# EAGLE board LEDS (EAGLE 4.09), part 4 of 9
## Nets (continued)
N$Y.22: LED11.64.P$K LED11.65.P$K LED11.66.P$K LED11.67.P$K LED11.68.P$K LED11.69.P$K LED11.70.P$K LED11.71.P$K LED11.72.P$K LED11.73.P$K LED11.74.P$K LED11.75.P$K LED11.76.P$K LED11.77.P$K LED11.78.P$K LED11.79.P$K LED11.80.P$K LED11.81.P$K LED11.82.P$K LED11.83.P$K LED11.84.P$K LED11.85.P$K LED11.86.P$K LED11.87.P$K LED11.88.P$K LED11.89.P$K LED11.90.P$K LED11.91.P$K LED11.92.P$K LED11.93.P$K LED11.94.P$K LED11.95.P$K LED11.96.P$K LED11.97.P$K LED11.98.P$K LED11.99.P$K LED11.100.P$K LED11.101.P$K LED11.102.P$K LED11.103.P$K LED11.104.P$K LED11.105.P$K LED11.106.P$K LED11.107.P$K LED11.108.P$K LED11.109.P$K LED11.110.P$K LED11.111.P$K LED11.112.P$K LED11.113.P$K LED11.114.P$K LED11.115.P$K LED11.116.P$K LED11.117.P$K LED11.118.P$K LED11.119.P$K LED11.120.P$K LED11.121.P$K LED11.122.P$K LED11.123.P$K LED11.124.P$K LED11.125.P$K LED11.126.P$K LED11.127.P$K Y.22.P$
N$Y.23: LED12.64.P$K LED12.65.P$K LED12.66.P$K LED12.67.P$K LED12.68.P$K LED12.69.P$K LED12.70.P$K LED12.71.P$K LED12.72.P$K LED12.73.P$K LED12.74.P$K LED12.75.P$K LED12.76.P$K LED12.77.P$K LED12.78.P$K LED12.79.P$K LED12.80.P$K LED12.81.P$K LED12.82.P$K LED12.83.P$K LED12.84.P$K LED12.85.P$K LED12.86.P$K LED12.87.P$K LED12.88.P$K LED12.89.P$K LED12.90.P$K LED12.91.P$K LED12.92.P$K LED12.93.P$K LED12.94.P$K LED12.95.P$K LED12.98.P$K LED12.99.P$K LED12.100.P$K LED12.101.P$K LED12.102.P$K LED12.103.P$K LED12.104.P$K LED12.105.P$K LED12.106.P$K LED12.107.P$K LED12.108.P$K LED12.109.P$K LED12.110.P$K LED12.111.P$K LED12.112.P$K LED12.113.P$K LED12.114.P$K LED12.115.P$K LED12.116.P$K LED12.117.P$K LED12.118.P$K LED12.119.P$K LED12.120.P$K LED12.121.P$K LED12.122.P$K LED12.123.P$K LED12.124.P$K LED12.125.P$K LED12.126.P$K LED12.127.P$K Y.23.P$
N$Y.24: LED13.64.P$K LED13.65.P$K LED13.66.P$K LED13.67.P$K LED13.68.P$K LED13.69.P$K LED13.70.P$K LED13.71.P$K LED13.72.P$K LED13.73.P$K LED13.74.P$K LED13.75.P$K LED13.76.P$K LED13.77.P$K LED13.78.P$K LED13.79.P$K LED13.80.P$K LED13.81.P$K LED13.82.P$K LED13.83.P$K LED13.84.P$K LED13.85.P$K LED13.86.P$K LED13.87.P$K LED13.88.P$K LED13.89.P$K LED13.90.P$K LED13.91.P$K LED13.92.P$K LED13.93.P$K LED13.94.P$K LED13.95.P$K LED13.96.P$K LED13.97.P$K LED13.98.P$K LED13.99.P$K LED13.100.P$K LED13.101.P$K LED13.102.P$K LED13.103.P$K LED13.104.P$K LED13.105.P$K LED13.106.P$K LED13.107.P$K LED13.108.P$K LED13.109.P$K LED13.110.P$K LED13.111.P$K LED13.112.P$K LED13.113.P$K LED13.114.P$K LED13.115.P$K LED13.116.P$K LED13.117.P$K LED13.118.P$K LED13.119.P$K LED13.120.P$K LED13.121.P$K LED13.122.P$K LED13.123.P$K LED13.124.P$K LED13.125.P$K LED13.126.P$K LED13.127.P$K Y.24.P$
N$Y.25: LED14.64.P$K LED14.65.P$K LED14.66.P$K LED14.67.P$K LED14.68.P$K LED14.69.P$K LED14.70.P$K LED14.71.P$K LED14.72.P$K LED14.73.P$K LED14.74.P$K LED14.75.P$K LED14.76.P$K LED14.77.P$K LED14.78.P$K LED14.79.P$K LED14.80.P$K LED14.81.P$K LED14.82.P$K LED14.83.P$K LED14.84.P$K LED14.85.P$K LED14.86.P$K LED14.87.P$K LED14.88.P$K LED14.89.P$K LED14.90.P$K LED14.91.P$K LED14.92.P$K LED14.93.P$K LED14.94.P$K LED14.95.P$K LED14.97.P$K LED14.99.P$K LED14.100.P$K LED14.101.P$K LED14.102.P$K LED14.103.P$K LED14.104.P$K LED14.105.P$K LED14.106.P$K LED14.107.P$K LED14.108.P$K LED14.109.P$K LED14.110.P$K LED14.111.P$K LED14.112.P$K LED14.113.P$K LED14.114.P$K LED14.115.P$K LED14.116.P$K LED14.117.P$K LED14.118.P$K LED14.119.P$K LED14.120.P$K LED14.121.P$K LED14.122.P$K LED14.123.P$K LED14.124.P$K LED14.125.P$K LED14.126.P$K LED14.127.P$K Y.25.P$
N$Y.26: LED15.64.P$K LED15.65.P$K LED15.66.P$K LED15.67.P$K LED15.68.P$K LED15.69.P$K LED15.70.P$K LED15.71.P$K LED15.72.P$K LED15.73.P$K LED15.74.P$K LED15.75.P$K LED15.76.P$K LED15.77.P$K LED15.78.P$K LED15.79.P$K LED15.80.P$K LED15.81.P$K LED15.82.P$K LED15.83.P$K LED15.84.P$K LED15.85.P$K LED15.86.P$K LED15.87.P$K LED15.88.P$K LED15.89.P$K LED15.90.P$K LED15.91.P$K LED15.92.P$K LED15.93.P$K LED15.94.P$K LED15.95.P$K LED15.97.P$K LED15.98.P$K LED15.99.P$K LED15.100.P$K LED15.101.P$K LED15.102.P$K LED15.103.P$K LED15.104.P$K LED15.105.P$K LED15.106.P$K LED15.107.P$K LED15.108.P$K LED15.109.P$K LED15.110.P$K LED15.111.P$K LED15.112.P$K LED15.113.P$K LED15.114.P$K LED15.115.P$K LED15.116.P$K LED15.117.P$K LED15.118.P$K LED15.119.P$K LED15.120.P$K LED15.121.P$K LED15.122.P$K LED15.123.P$K LED15.124.P$K LED15.125.P$K LED15.126.P$K LED15.127.P$K Y.26.P$
N$Y.27: LED16.64.P$K LED16.65.P$K LED16.66.P$K LED16.67.P$K LED16.68.P$K LED16.69.P$K LED16.70.P$K LED16.71.P$K LED16.72.P$K LED16.73.P$K LED16.74.P$K LED16.75.P$K LED16.76.P$K LED16.77.P$K LED16.78.P$K LED16.79.P$K LED16.80.P$K LED16.81.P$K LED16.82.P$K LED16.83.P$K LED16.84.P$K LED16.85.P$K LED16.86.P$K LED16.87.P$K LED16.88.P$K LED16.89.P$K LED16.90.P$K LED16.91.P$K LED16.92.P$K LED16.93.P$K LED16.94.P$K LED16.95.P$K LED16.97.P$K LED16.98.P$K LED16.99.P$K LED16.100.P$K LED16.101.P$K LED16.102.P$K LED16.103.P$K LED16.104.P$K LED16.105.P$K LED16.106.P$K LED16.107.P$K LED16.108.P$K LED16.109.P$K LED16.110.P$K LED16.111.P$K LED16.112.P$K LED16.113.P$K LED16.114.P$K LED16.115.P$K LED16.116.P$K LED16.117.P$K LED16.118.P$K LED16.119.P$K LED16.120.P$K LED16.121.P$K LED16.122.P$K LED16.123.P$K LED16.124.P$K LED16.125.P$K LED16.126.P$K LED16.127.P$K Y.27.P$
N$Y.28: LED17.64.P$K LED17.65.P$K LED17.66.P$K LED17.67.P$K LED17.68.P$K LED17.69.P$K LED17.70.P$K LED17.71.P$K LED17.72.P$K LED17.73.P$K LED17.74.P$K LED17.75.P$K LED17.76.P$K LED17.77.P$K LED17.78.P$K LED17.79.P$K LED17.80.P$K LED17.81.P$K LED17.82.P$K LED17.83.P$K LED17.84.P$K LED17.85.P$K LED17.86.P$K LED17.87.P$K LED17.88.P$K LED17.89.P$K LED17.90.P$K LED17.91.P$K LED17.92.P$K LED17.93.P$K LED17.94.P$K LED17.95.P$K LED17.97.P$K LED17.98.P$K LED17.99.P$K LED17.100.P$K LED17.101.P$K LED17.102.P$K LED17.103.P$K LED17.104.P$K LED17.105.P$K LED17.106.P$K LED17.107.P$K LED17.108.P$K LED17.109.P$K LED17.110.P$K LED17.111.P$K LED17.112.P$K LED17.113.P$K LED17.114.P$K LED17.115.P$K LED17.116.P$K LED17.117.P$K LED17.118.P$K LED17.119.P$K LED17.120.P$K LED17.121.P$K LED17.122.P$K LED17.123.P$K LED17.124.P$K LED17.125.P$K LED17.126.P$K LED17.127.P$K Y.28.P$
N$Y.29: LED18.64.P$K LED18.65.P$K LED18.66.P$K LED18.67.P$K LED18.68.P$K LED18.69.P$K LED18.70.P$K LED18.71.P$K LED18.72.P$K LED18.73.P$K LED18.74.P$K LED18.75.P$K LED18.76.P$K LED18.77.P$K LED18.78.P$K LED18.79.P$K LED18.80.P$K LED18.81.P$K LED18.82.P$K LED18.83.P$K LED18.84.P$K LED18.85.P$K LED18.86.P$K LED18.87.P$K LED18.88.P$K LED18.89.P$K LED18.90.P$K LED18.91.P$K LED18.92.P$K LED18.93.P$K LED18.94.P$K LED18.95.P$K LED18.96.P$K LED18.98.P$K LED18.99.P$K LED18.100.P$K LED18.101.P$K LED18.102.P$K LED18.103.P$K LED18.104.P$K LED18.105.P$K LED18.106.P$K LED18.107.P$K LED18.108.P$K LED18.109.P$K LED18.110.P$K LED18.111.P$K LED18.112.P$K LED18.113.P$K LED18.114.P$K LED18.115.P$K LED18.116.P$K LED18.117.P$K LED18.118.P$K LED18.119.P$K LED18.120.P$K LED18.121.P$K LED18.122.P$K LED18.123.P$K LED18.124.P$K LED18.125.P$K LED18.126.P$K LED18.127.P$K Y.29.P$
N$Y.30: LED19.64.P$K LED19.65.P$K LED19.66.P$K LED19.67.P$K LED19.68.P$K LED19.69.P$K LED19.70.P$K LED19.71.P$K LED19.72.P$K LED19.73.P$K LED19.74.P$K LED19.75.P$K LED19.76.P$K LED19.77.P$K LED19.78.P$K LED19.79.P$K LED19.80.P$K LED19.81.P$K LED19.82.P$K LED19.83.P$K LED19.84.P$K LED19.85.P$K LED19.86.P$K LED19.87.P$K LED19.88.P$K LED19.89.P$K LED19.90.P$K LED19.91.P$K LED19.92.P$K LED19.93.P$K LED19.94.P$K LED19.96.P$K LED19.97.P$K LED19.98.P$K LED19.99.P$K LED19.100.P$K LED19.101.P$K LED19.102.P$K LED19.103.P$K LED19.104.P$K LED19.105.P$K LED19.106.P$K LED19.107.P$K LED19.108.P$K LED19.109.P$K LED19.110.P$K LED19.111.P$K LED19.112.P$K LED19.113.P$K LED19.114.P$K LED19.115.P$K LED19.116.P$K LED19.117.P$K LED19.118.P$K LED19.119.P$K LED19.120.P$K LED19.121.P$K LED19.122.P$K LED19.123.P$K LED19.124.P$K LED19.125.P$K LED19.126.P$K LED19.127.P$K Y.30.P$
N$Y.31: LED20.64.P$K LED20.65.P$K LED20.66.P$K LED20.67.P$K LED20.68.P$K LED20.69.P$K LED20.70.P$K LED20.71.P$K LED20.72.P$K LED20.73.P$K LED20.74.P$K LED20.75.P$K LED20.76.P$K LED20.77.P$K LED20.78.P$K LED20.79.P$K LED20.80.P$K LED20.81.P$K LED20.82.P$K LED20.83.P$K LED20.84.P$K LED20.85.P$K LED20.86.P$K LED20.87.P$K LED20.88.P$K LED20.89.P$K LED20.90.P$K LED20.91.P$K LED20.92.P$K LED20.93.P$K LED20.94.P$K LED20.96.P$K LED20.97.P$K LED20.98.P$K LED20.99.P$K LED20.100.P$K LED20.101.P$K LED20.102.P$K LED20.103.P$K LED20.104.P$K LED20.105.P$K LED20.106.P$K LED20.107.P$K LED20.108.P$K LED20.109.P$K LED20.110.P$K LED20.111.P$K LED20.112.P$K LED20.113.P$K LED20.114.P$K LED20.115.P$K LED20.116.P$K LED20.117.P$K LED20.118.P$K LED20.119.P$K LED20.120.P$K LED20.121.P$K LED20.122.P$K LED20.123.P$K LED20.124.P$K LED20.125.P$K LED20.126.P$K LED20.127.P$K Y.31.P$
N$Y.32: LED14.96.P$K
N$Y.33: LED14.98.P$K
N$Y.34: LED14.128.P$K
N$Y.35: LED14.129.P$K
N$Y.36: LED14.130.P$K
N$Y.37: LED14.131.P$K
N$Y.38: LED14.132.P$K
N$Y.39: LED14.133.P$K
S$2: LED0.12.P$K LED0.13.P$K LED0.14.P$K
S$3: LED0.62.P$A LED1.62.P$A
S$4: LED0.60.P$A LED1.60.P$A LED2.60.P$A
S$5: LED0.59.P$A LED1.59.P$A
S$6: LED3.57.P$A LED4.57.P$A
S$7: LED5.61.P$K LED5.62.P$K
S$8: LED2.62.P$A LED3.62.P$A
S$9: LED2.58.P$K LED2.59.P$K LED2.60.P$K LED2.61.P$K LED2.62.P$K
S$10: LED3.58.P$K LED3.59.P$K LED3.60.P$K LED3.61.P$K LED3.62.P$K
S$11: LED0.61.P$A LED1.61.P$A LED2.61.P$A LED3.61.P$A
S$12: LED0.57.P$A LED1.57.P$A LED2.57.P$A
S$13: LED0.56.P$A LED1.56.P$A LED2.56.P$A LED3.56.P$A X56.P$
S$14: LED7.61.P$K LED7.62.P$K LED7.63.P$K
S$15: LED6.61.P$K LED6.62.P$K LED6.63.P$K
S$16: LED1.61.P$K LED1.62.P$K
S$17: LED2.59.P$A LED3.59.P$A LED4.59.P$A
S$18: LED1.59.P$K LED1.60.P$K
S$19: LED0.55.P$A LED1.55.P$A LED2.55.P$A X55.P$
S$20: LED3.23.P$A LED4.23.P$A LED5.23.P$A
S$21: LED3.55.P$A LED4.55.P$A
S$22: LED1.54.P$A LED2.54.P$A LED3.54.P$A LED4.54.P$A
S$25: LED6.61.P$A LED7.61.P$A
S$26: LED8.62.P$K LED8.63.P$K
S$27: LED8.59.P$K LED8.60.P$K
S$28: LED4.56.P$A LED5.56.P$A
S$29: LED8.0.P$K LED8.1.P$K LED8.2.P$K LED8.3.P$K LED8.4.P$K LED8.5.P$K LED8.6.P$K LED8.7.P$K LED8.8.P$K LED8.9.P$K LED8.10.P$K LED8.11.P$K LED8.12.P$K LED8.13.P$K LED8.14.P$K LED8.15.P$K LED8.16.P$K LED8.17.P$K LED8.18.P$K LED8.19.P$K LED8.20.P$K LED8.21.P$K LED8.22.P$K LED8.23.P$K LED8.24.P$K LED8.25.P$K LED8.26.P$K LED8.27.P$K Y.8.P$
S$30: LED2.33.P$K LED2.34.P$K
S$31: LED6.23.P$A LED7.23.P$A LED8.23.P$A LED9.23.P$A
S$32: LED4.25.P$A LED5.25.P$A LED6.25.P$A
S$33: LED3.25.P$K LED3.26.P$K LED3.27.P$K LED3.28.P$K LED3.29.P$K LED3.30.P$K LED3.31.P$K
S$34: LED4.25.P$K LED4.26.P$K LED4.27.P$K LED4.28.P$K LED4.29.P$K LED4.30.P$K
S$35: LED4.26.P$A LED5.26.P$A
S$36: LED4.30.P$A
S$37: LED4.46.P$K LED4.47.P$K LED4.48.P$K LED4.49.P$K LED4.50.P$K LED4.51.P$K LED4.52.P$K LED4.53.P$K LED4.54.P$K LED4.55.P$K
S$38: LED5.26.P$K LED5.27.P$K LED5.28.P$K
S$39: LED6.41.P$K LED6.42.P$K LED6.43.P$K LED6.44.P$K LED6.45.P$K LED6.46.P$K LED6.47.P$K LED6.48.P$K
S$40: LED3.28.P$A LED4.28.P$A LED5.28.P$A
S$41: LED5.48.P$K LED5.49.P$K LED5.50.P$K LED5.51.P$K LED5.52.P$K LED5.53.P$K LED5.54.P$K LED5.55.P$K
S$42: LED5.36.P$A LED6.36.P$A
S$43: LED7.31.P$K LED7.33.P$K LED7.34.P$K LED7.35.P$K LED7.36.P$K LED7.37.P$K LED7.38.P$K LED7.39.P$K LED7.40.P$K LED7.41.P$K LED7.42.P$K LED7.43.P$K LED7.44.P$K LED7.45.P$K LED7.46.P$K LED7.47.P$K
S$44: LED4.31.P$A LED5.31.P$A LED6.31.P$A
S$45: LED4.34.P$K LED4.35.P$K
S$46: LED6.31.P$K
S$47: LED0.54.P$A X54.P$
S$48: LED5.33.P$K LED5.34.P$K LED5.35.P$K LED5.36.P$K
S$49: LED3.48.P$K LED3.49.P$K LED3.50.P$K LED3.51.P$K LED3.52.P$K LED3.53.P$K LED3.54.P$K LED3.55.P$K
S$50: LED4.24.P$A LED5.24.P$A LED6.24.P$A LED7.24.P$A LED8.24.P$A LED9.24.P$A LED10.24.P$A
S$51: LED1.54.P$K LED1.55.P$K LED1.56.P$K LED1.57.P$K
S$52: LED3.32.P$K LED3.33.P$K LED3.34.P$K
S$53: LED5.29.P$K LED5.31.P$K LED5.32.P$K
S$54: LED5.33.P$A LED6.33.P$A
S$55: LED2.42.P$K LED2.43.P$K LED2.44.P$K LED2.45.P$K LED2.46.P$K LED2.47.P$K LED2.48.P$K LED2.49.P$K LED2.50.P$K LED2.51.P$K LED2.52.P$K LED2.53.P$K LED2.54.P$K LED2.55.P$K LED2.56.P$K LED2.57.P$K
S$56: LED4.34.P$A LED5.34.P$A
S$57: LED4.31.P$K LED4.32.P$K LED4.33.P$K
S$58: LED5.32.P$A
S$59: LED1.19.P$A LED2.19.P$A LED3.19.P$A LED4.19.P$A LED5.19.P$A LED6.19.P$A LED7.19.P$A LED8.19.P$A LED9.19.P$A
S$60: LED6.33.P$K LED6.34.P$K LED6.35.P$K
S$61: LED10.0.P$K LED10.1.P$K LED10.2.P$K LED10.3.P$K LED10.4.P$K LED10.5.P$K LED10.6.P$K LED10.7.P$K LED10.8.P$K LED10.9.P$K LED10.10.P$K LED10.11.P$K LED10.12.P$K LED10.13.P$K LED10.14.P$K LED10.15.P$K LED10.16.P$K LED10.17.P$K LED10.18.P$K LED10.19.P$K LED10.20.P$K LED10.21.P$K LED10.22.P$K LED10.23.P$K LED10.24.P$K LED10.25.P$K LED10.26.P$K LED10.27.P$K LED10.28.P$K Y.10.P$
S$62: LED4.38.P$K LED4.39.P$K LED4.40.P$K
S$63: LED9.0.P$K LED9.1.P$K LED9.2.P$K LED9.3.P$K LED9.4.P$K LED9.5.P$K LED9.6.P$K LED9.7.P$K LED9.8.P$K LED9.9.P$K LED9.10.P$K LED9.11.P$K LED9.12.P$K LED9.13.P$K LED9.14.P$K LED9.15.P$K LED9.16.P$K LED9.17.P$K LED9.18.P$K LED9.19.P$K LED9.20.P$K LED9.21.P$K LED9.22.P$K LED9.23.P$K LED9.24.P$K LED9.25.P$K LED9.26.P$K Y.9.P$
S$64: LED4.27.P$A LED5.27.P$A LED6.27.P$A LED7.27.P$A LED8.27.P$A LED9.27.P$A LED10.27.P$A
S$65: LED3.35.P$K LED3.37.P$K LED3.38.P$K
S$66: LED5.40.P$A LED6.40.P$A
S$67: LED6.36.P$K LED6.37.P$K LED6.38.P$K LED6.39.P$K LED6.40.P$K
S$68: LED3.42.P$A LED4.42.P$A
S$69: LED3.45.P$A LED4.45.P$A LED5.45.P$A
S$70: LED5.37.P$K LED5.38.P$K LED5.39.P$K LED5.40.P$K LED5.41.P$K
S$71: LED3.44.P$A LED4.44.P$A LED5.44.P$A LED6.44.P$A
S$72: LED4.44.P$K LED4.45.P$K
S$73: LED2.21.P$A LED3.21.P$A LED4.21.P$A LED5.21.P$A LED6.21.P$A
S$74: LED2.37.P$K
S$75: LED3.38.P$A LED4.38.P$A LED5.38.P$A LED6.38.P$A
S$76: LED3.22.P$A LED4.22.P$A LED5.22.P$A
S$77: LED4.21.P$K LED4.22.P$K LED4.23.P$K LED4.24.P$K
S$78: LED5.42.P$K LED5.43.P$K LED5.44.P$K
S$79: LED5.42.P$A LED6.42.P$A LED7.42.P$A LED8.42.P$A
S$80: LED3.41.P$A LED4.41.P$A LED5.41.P$A LED6.41.P$A LED7.41.P$A
S$81: LED7.45.P$A LED8.45.P$A
S$82: LED0.20.P$A LED1.20.P$A
S$83: LED0.12.P$A X12.P$
S$84: LED0.10.P$A X10.P$
S$85: LED0.14.P$A X14.P$
S$86: LED0.17.P$K LED0.18.P$K
S$87: LED0.13.P$A X13.P$
S$88: LED0.9.P$K LED0.10.P$K
S$89: LED0.9.P$A X9.P$
S$90: LED0.11.P$A X11.P$
S$91: LED4.18.P$K LED4.19.P$K LED4.20.P$K
S$92: LED2.34.P$A LED3.34.P$A
S$93: LED2.35.P$A LED3.35.P$A LED4.35.P$A
S$94: LED2.33.P$A LED3.33.P$A LED4.33.P$A
S$95: LED6.0.P$K LED6.1.P$K LED6.2.P$K LED6.3.P$K LED6.4.P$K LED6.5.P$K LED6.6.P$K LED6.7.P$K LED6.8.P$K LED6.9.P$K LED6.10.P$K LED6.11.P$K LED6.12.P$K Y.6.P$
S$96: LED3.32.P$A LED4.32.P$A
S$97: LED2.31.P$A LED3.31.P$A
S$98: LED2.18.P$A LED3.18.P$A LED4.18.P$A
S$99: LED11.27.P$A LED12.27.P$A
S$100: LED6.30.P$A LED7.30.P$A LED8.30.P$A LED9.30.P$A LED10.30.P$A LED11.30.P$A LED12.30.P$A LED13.30.P$A LED14.30.P$A LED15.30.P$A LED16.30.P$A
S$101: LED7.44.P$A LED8.44.P$A LED9.44.P$A LED10.44.P$A LED11.44.P$A LED12.44.P$A
S$102: LED4.47.P$A LED5.47.P$A LED6.47.P$A LED7.47.P$A LED8.47.P$A LED9.47.P$A LED10.47.P$A LED11.47.P$A
S$103: LED7.48.P$A LED8.48.P$A LED9.48.P$A LED10.48.P$A
S$104: LED5.43.P$A LED6.43.P$A LED7.43.P$A LED8.43.P$A LED9.43.P$A LED10.43.P$A LED11.43.P$A
S$105: LED2.51.P$A LED3.51.P$A LED4.51.P$A LED5.51.P$A LED6.51.P$A LED7.51.P$A LED8.51.P$A LED9.51.P$A LED10.51.P$A LED11.51.P$A LED12.51.P$A LED13.51.P$A LED14.51.P$A
S$106: LED9.53.P$K LED9.54.P$K LED9.55.P$K LED9.56.P$K LED9.57.P$K LED9.58.P$K LED9.59.P$K LED9.60.P$K LED9.61.P$K LED9.62.P$K LED9.63.P$K
S$107: LED12.44.P$K LED12.45.P$K LED12.46.P$K LED12.47.P$K LED12.48.P$K LED12.49.P$K LED12.50.P$K LED12.51.P$K LED12.52.P$K LED12.53.P$K LED12.54.P$K LED12.55.P$K LED12.56.P$K LED12.57.P$K LED12.58.P$K LED12.59.P$K LED12.60.P$K LED12.61.P$K LED12.62.P$K LED12.63.P$K
S$108: LED2.53.P$A LED3.53.P$A LED4.53.P$A LED5.53.P$A LED6.53.P$A LED7.53.P$A LED8.53.P$A LED9.53.P$A LED10.53.P$A LED11.53.P$A
S$109: LED7.51.P$K LED7.52.P$K LED7.53.P$K LED7.54.P$K LED7.55.P$K LED7.56.P$K
S$110: LED3.52.P$A LED4.52.P$A LED5.52.P$A LED6.52.P$A LED7.52.P$A LED8.52.P$A LED9.52.P$A
S$111: LED6.55.P$A LED7.55.P$A LED8.55.P$A LED9.55.P$A LED10.55.P$A
S$112: LED9.48.P$K LED9.49.P$K LED9.50.P$K
S$113: LED9.51.P$K LED9.52.P$K
S$114: LED7.48.P$K LED7.49.P$K LED7.50.P$K
S$115: LED6.50.P$K LED6.51.P$K LED6.52.P$K LED6.53.P$K LED6.54.P$K LED6.55.P$K
S$116: LED5.45.P$K LED5.46.P$K LED5.47.P$K
S$117: LED3.42.P$K LED3.43.P$K LED3.44.P$K LED3.45.P$K LED3.46.P$K LED3.47.P$K
S$118: LED3.48.P$A LED4.48.P$A
S$119: LED8.49.P$K LED8.50.P$K LED8.51.P$K LED8.52.P$K LED8.53.P$K LED8.54.P$K LED8.55.P$K LED8.56.P$K LED8.57.P$K LED8.58.P$K
S$120: LED3.49.P$A LED4.49.P$A LED5.49.P$A LED6.49.P$A LED7.49.P$A LED8.49.P$A LED9.49.P$A LED10.49.P$A
S$121: LED13.48.P$A LED14.48.P$A LED15.48.P$A
S$122: LED15.49.P$K LED15.50.P$K LED15.51.P$K LED15.52.P$K LED15.53.P$K LED15.54.P$K LED15.55.P$K LED15.56.P$K LED15.57.P$K LED15.58.P$K LED15.59.P$K LED15.60.P$K LED15.61.P$K LED15.62.P$K LED15.63.P$K
S$123: LED17.47.P$K LED17.48.P$K LED17.49.P$K LED17.50.P$K LED17.51.P$K LED17.52.P$K LED17.53.P$K LED17.54.P$K LED17.55.P$K LED17.56.P$K LED17.57.P$K LED17.58.P$K LED17.59.P$K LED17.60.P$K LED17.61.P$K LED17.62.P$K LED17.63.P$K
S$124: LED7.40.P$A LED8.40.P$A LED9.40.P$A LED10.40.P$A LED11.40.P$A LED12.40.P$A LED13.40.P$A LED14.40.P$A LED15.40.P$A LED16.40.P$A
S$125: LED10.29.P$K LED10.30.P$K LED10.31.P$K LED10.33.P$K LED10.34.P$K LED10.35.P$K LED10.36.P$K LED10.37.P$K
S$126: LED9.31.P$K LED9.33.P$K LED9.34.P$K
S$127: LED9.27.P$K LED9.28.P$K LED9.29.P$K LED9.30.P$K
S$128: LED1.11.P$A LED2.11.P$A LED3.11.P$A LED4.11.P$A LED5.11.P$A LED6.11.P$A
S$129: LED5.0.P$K LED5.1.P$K LED5.2.P$K LED5.3.P$K LED5.4.P$K Y.5.P$
S$130: LED4.0.P$K LED4.1.P$K Y.4.P$
S$131: LED1.1.P$A LED2.1.P$A LED3.1.P$A LED4.1.P$A
S$132: LED2.0.P$K LED2.1.P$K Y.2.P$
S$133: LED1.0.P$K LED1.1.P$K Y.1.P$
S$134: LED0.1.P$A X1.P$
S$135: LED0.2.P$A X2.P$
S$136: LED0.7.P$A X7.P$
S$427: LED18.127.P$A
S$428: LED15.127.P$A
S$516: LED17.127.P$A
S$518: LED19.127.P$A

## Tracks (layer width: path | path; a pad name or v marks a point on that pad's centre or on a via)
LED2.27  (18 unrouted)
N$X.0  (32 unrouted)
N$X.1  (26 unrouted)
N$X.2  (30 unrouted)
N$X.3  (32 unrouted)
N$X.4  (32 unrouted)
N$X.5  (32 unrouted)
N$X.6  (32 unrouted)
N$X.7  (30 unrouted)
N$X.8  (32 unrouted)
N$X.9  (30 unrouted)
N$X.10  (30 unrouted)
N$X.11  (24 unrouted)
N$X.12  (30 unrouted)
N$X.13  (30 unrouted)
N$X.14  (30 unrouted)
N$X.15  (30 unrouted)
N$X.16  (30 unrouted)
N$X.17  (30 unrouted)
N$X.18  (26 unrouted)
N$X.19  (20 unrouted)
N$X.20  (28 unrouted)
N$X.21  (24 unrouted)
N$X.22  (25 unrouted)
N$X.23  (21 unrouted)
N$X.24  (19 unrouted)
N$X.25  (24 unrouted)
N$X.26  (24 unrouted)
N$X.27  (via drill 0.2)  (1 unrouted)
  Bottom 0.2: 29.81,23.11 30.35,22.56
  other vias: 30.4,22.47
N$X.28  (25 unrouted)
N$X.29  (28 unrouted)
N$X.30  (14 unrouted)
N$X.31  (22 unrouted)
N$X.32  (7 unrouted)
N$X.33  (20 unrouted)
N$X.34  (23 unrouted)
N$X.35  (23 unrouted)
N$X.36  (24 unrouted)
N$X.37  (25 unrouted)
N$X.38  (24 unrouted)
N$X.39  (26 unrouted)
N$X.40  (14 unrouted)
N$X.41  (23 unrouted)
N$X.42  (22 unrouted)
N$X.43  (19 unrouted)
N$X.44  (18 unrouted)
N$X.45  (22 unrouted)
N$X.46  (28 unrouted)
N$X.47  (19 unrouted)
N$X.48  (15 unrouted)
N$X.49  (19 unrouted)
N$X.50  (28 unrouted)
N$X.51  (16 unrouted)
N$X.52  (21 unrouted)
N$X.53  (19 unrouted)
N$X.54  (25 unrouted)
N$X.55  (20 unrouted)
N$X.56  (23 unrouted)
N$X.57  (23 unrouted)
N$X.58  (22 unrouted)
N$X.59  (23 unrouted)
N$X.60  (22 unrouted)
N$X.61  (22 unrouted)
N$X.62  (25 unrouted)
N$X.63  (25 unrouted)
N$X.64  (via drill 0.2)  (1 unrouted)
  Bottom 0.2: 31.58,23.13 32.13,22.58
  other vias: 32.18,22.49
N$X.65  (via drill 0.2)  (1 unrouted)
  Bottom 0.2: 33.41,23.09 33.95,22.54
  other vias: 34,22.45
N$X.66  (via drill 0.2)  (1 unrouted)
  Bottom 0.2: 35.2,23.09 35.75,22.54
  other vias: 35.8,22.45
N$X.67  (via drill 0.2)  (1 unrouted)
  Bottom 0.2: 37,23.06 37.55,22.52
  other vias: 37.6,22.43
N$X.68  (via drill 0.2)  (1 unrouted)
  Bottom 0.2: 38.8,23.09 39.35,22.54
  other vias: 39.4,22.45
N$X.69  (via drill 0.2)  (1 unrouted)
  Bottom 0.2: 27.96,20.5 28.51,19.95
  other vias: 28.56,19.86
N$X.70  (via drill 0.2)  (1 unrouted)
  Bottom 0.2: 29.83,20.47 30.37,19.93
  other vias: 30.43,19.84
N$X.71  (via drill 0.2)  (1 unrouted)
  Bottom 0.2: 31.63,20.52 32.17,19.97
  other vias: 32.23,19.88
N$X.72  (via drill 0.2)  (1 unrouted)
  Bottom 0.2: 33.43,20.52 33.97,19.97
  other vias: 34.02,19.88
N$X.73  (via drill 0.2)  (1 unrouted)
  Bottom 0.2: 35.2,20.54 35.75,20
  other vias: 35.8,19.9
N$X.74  (via drill 0.2)  (1 unrouted)
  Bottom 0.2: 36.98,20.54 37.53,20
  other vias: 37.58,19.9
N$X.75  (via drill 0.2)  (1 unrouted)
  Bottom 0.2: 38.78,20.52 39.33,19.97
  other vias: 39.38,19.88
N$X.76  (via drill 0.2)  (1 unrouted)
  Bottom 0.2: 38.78,17.95 39.33,17.4
  other vias: 39.38,17.31
N$X.77  (via drill 0.2)  (1 unrouted)
  Bottom 0.2: 37.05,17.93 37.59,17.38
  other vias: 37.65,17.29
N$X.78  (via drill 0.2)  (1 unrouted)
  Bottom 0.2: 35.23,17.93 35.77,17.38
  other vias: 35.82,17.29
N$X.79  (via drill 0.2)  (1 unrouted)
  Bottom 0.2: 33.41,17.93 33.95,17.38
  other vias: 34,17.29
N$X.80  (via drill 0.2)  (1 unrouted)
  Bottom 0.2: 31.63,17.93 32.17,17.38
  other vias: 32.23,17.29
N$X.81  (via drill 0.2)  (1 unrouted)
  Bottom 0.2: 29.83,17.89 30.37,17.34
  other vias: 30.43,17.25
N$X.82  (via drill 0.2)  (1 unrouted)
  Bottom 0.2: 28.03,17.95 28.57,17.4
  other vias: 28.63,17.31
N$X.83  (via drill 0.2)  (1 unrouted)
  Bottom 0.2: 35.2,10.22 35.75,9.68
  other vias: 35.8,9.59
N$X.84  (via drill 0.2)  (1 unrouted)
  Bottom 0.2: 36.98,10.2 37.53,9.66
  other vias: 37.58,9.56
N$X.85  (via drill 0.2)  (1 unrouted)
  Bottom 0.2: 38.8,10.22 39.35,9.68
  other vias: 39.4,9.59
N$X.86  (via drill 0.2)  (1 unrouted)
  Bottom 0.2: 38.8,7.57 39.35,7.02
  other vias: 39.4,6.93
N$X.87  (via drill 0.2)  (1 unrouted)
  Bottom 0.2: 37,7.59 37.55,7.05
  other vias: 37.6,6.95
N$X.88  (via drill 0.2)  (1 unrouted)
  Bottom 0.2: 35.18,7.57 35.73,7.02
  other vias: 35.78,6.93
N$X.89  (via drill 0.2)  (1 unrouted)
  Bottom 0.2: 35.2,4.91 35.75,4.37
  other vias: 35.8,4.27
N$X.90  (via drill 0.2)  (1 unrouted)
  Bottom 0.2: 37,4.96 37.55,4.41
  other vias: 37.6,4.32
N$X.91  (via drill 0.2)  (1 unrouted)
  Bottom 0.2: 38.8,4.89 39.35,4.35
  other vias: 39.4,4.25
N$X.92  (via drill 0.2)  (4 unrouted)
  Top 0.8: 35.84,1.71 35.84,84.31
  Bottom 0.2: 35.2,2.34 35.75,1.8 | 35.28,15.43 35.82,14.88
  other vias: 35.8,1.71 35.88,14.79
N$X.93  (via drill 0.2)  (1 unrouted)
  Bottom 0.2: 113.85,64.68 113.31,65.22
  other vias: 113.91,64.58
N$X.94  (via drill 0.2)  (2 unrouted)
  Top 0.8: 37.6,1.65 37.62,85.02
  Bottom 0.2: 37.03,2.34 37.57,1.8
  other vias: 37.62,1.71
N$X.95  (via drill 0.2)  (2 unrouted)
  Top 0.8: 39.42,1.71 39.44,85.02
  Bottom 0.2: 38.85,2.39 39.39,1.84
  other vias: 39.45,1.75
N$X.96  (via drill 0.2)  (1 unrouted)
  Bottom 0.2: 29.83,83.31 30.38,82.76
  other vias: 30.43,82.67
N$X.97  (via drill 0.2)  (1 unrouted)
  Bottom 0.2: 31.64,83.33 32.19,82.79
  other vias: 32.24,82.69
N$X.98  (via drill 0.2)  (1 unrouted)
  Bottom 0.2: 113.85,62.03 113.31,62.58
  other vias: 113.91,61.94
N$X.99  (via drill 0.2)  (1 unrouted)
  Bottom 0.2: 113.77,54.02 113.23,54.56
  other vias: 113.83,53.92
N$X.100  (via drill 0.2)  (1 unrouted)
  Bottom 0.2: 33.43,83.31 33.97,82.76
  other vias: 34.03,82.67
N$X.101  (via drill 0.2)  (1 unrouted)
  Bottom 0.2: 113.17,51.95 113.72,51.4
  other vias: 113.77,51.31
N$X.102  (via drill 0.2)  (1 unrouted)
  Bottom 0.2: 35.19,83.31 35.74,82.76
  other vias: 35.79,82.67
N$X.103  (via drill 0.2)  (1 unrouted)
  Bottom 0.2: 36.95,83.33 37.5,82.79
  other vias: 37.55,82.69
N$X.104  (via drill 0.2)  (1 unrouted)
  Bottom 0.2: 113.17,49.36 113.72,48.81
  other vias: 113.77,48.72
N$X.105  (via drill 0.2)  (1 unrouted)
  Bottom 0.2: 38.79,83.33 39.34,82.79
  other vias: 39.39,82.69
N$X.106  (via drill 0.2)  (1 unrouted)
  Bottom 0.2: 29.83,80.71 30.38,80.17
  other vias: 30.43,80.08
N$X.107  (via drill 0.2)  (1 unrouted)
  Bottom 0.2: 31.62,80.71 32.16,80.17
  other vias: 32.22,80.08
N$X.108  (via drill 0.2)  (1 unrouted)
  Bottom 0.2: 33.4,80.69 33.95,80.14
  other vias: 34,80.05
N$X.109  (via drill 0.2)  (1 unrouted)
  Bottom 0.2: 35.19,80.71 35.74,80.17
  other vias: 35.79,80.08
N$X.110  (via drill 0.2)  (1 unrouted)
  Bottom 0.2: 37,80.71 37.55,80.17
  other vias: 37.6,80.08
N$X.111  (via drill 0.2)  (1 unrouted)
  Bottom 0.2: 38.84,80.77 39.38,80.22
  other vias: 39.44,80.13
N$X.112  (via drill 0.2)  (1 unrouted)
  Bottom 0.2: 29.86,78.1 30.4,77.55
  other vias: 30.45,77.46
N$X.113  (via drill 0.2)  (1 unrouted)
  Bottom 0.2: 31.59,78.12 32.14,77.58
  other vias: 32.19,77.48
N$X.114  (via drill 0.2)  (1 unrouted)
  Bottom 0.2: 33.4,78.15 33.95,77.6
  other vias: 34,77.51
N$X.115  (via drill 0.2)  (1 unrouted)
  Bottom 0.2: 35.19,78.17 35.74,77.63
  other vias: 35.79,77.53
N$X.116  (via drill 0.2)  (1 unrouted)
  Bottom 0.2: 37.03,78.15 37.57,77.6
  other vias: 37.63,77.51
N$X.117  (via drill 0.2)  (1 unrouted)
  Bottom 0.2: 38.84,78.12 39.38,77.58
  other vias: 39.44,77.48
N$X.118  (via drill 0.2)  (1 unrouted)
  Bottom 0.2: 38.77,75.53 39.31,74.98
  other vias: 39.36,74.89
N$X.119  (via drill 0.2)  (1 unrouted)
  Bottom 0.2: 40.6,12.81 41.15,12.26
  other vias: 41.2,12.17
N$X.121  (via drill 0.2)  (1 unrouted)
  Bottom 0.2: 42.38,12.88 42.92,12.33
  other vias: 42.98,12.24
N$X.122  (via drill 0.2)  (1 unrouted)
  Bottom 0.2: 44.27,12.79 44.81,12.24
  other vias: 44.87,12.15
N$X.123  (via drill 0.2)  (1 unrouted)
  Bottom 0.2: 44.25,10.2 44.79,9.65
  other vias: 44.84,9.56
N$X.124  (via drill 0.2)  (1 unrouted)
  Bottom 0.2: 42.4,10.18 42.95,9.63
  other vias: 43,9.54
N$X.125  (via drill 0.2)  (1 unrouted)
  Bottom 0.2: 40.6,10.18 41.15,9.63
  other vias: 41.2,9.54
N$X.126  (via drill 0.2)  (1 unrouted)
  Bottom 0.2: 40.65,7.59 41.19,7.05
  other vias: 41.25,6.95
N$X.127  (via drill 0.2)  (1 unrouted)
  Bottom 0.2: 42.38,7.59 42.92,7.05
  other vias: 42.98,6.95
N$X.128  (via drill 0.2)  (1 unrouted)
  Bottom 0.2: 44.22,7.59 44.77,7.05
  other vias: 44.82,6.95
N$X.129  (via drill 0.2)  (1 unrouted)
  Bottom 0.2: 112.06,38.45 111.52,39 111.17,39
  other vias: 112.02,38.43
N$X.130  (via drill 0.2)  (1 unrouted)
  Bottom 0.2: 44.22,4.9 44.77,4.35
  other vias: 44.82,4.26
N$X.131  (via drill 0.2)  (1 unrouted)
  Bottom 0.2: 42.47,4.9 43.02,4.35
  other vias: 43.07,4.26
N$X.132  (via drill 0.2)
  other vias: 111.92,46.23
N$X.133  (via drill 0.2)  (1 unrouted)
  Bottom 0.2: 40.6,4.9 41.15,4.35
  other vias: 41.2,4.26
N$X.134  (via drill 0.2)  (2 unrouted)
  Top 0.8: 41.21,1.71 41.19,84.99
  Bottom 0.2: 40.63,2.36 41.17,1.81
  other vias: 41.23,1.72
N$X.135  (via drill 0.2)  (4 unrouted)
  Top 0.8: 43.04,1.71 43.02,84.92
  Bottom 0.2: 42.47,2.33 43.02,1.79 | 42.44,75.56 42.98,75.01
  other vias: 43.07,1.7 43.03,74.92
N$X.136  (via drill 0.2)  (2 unrouted)
  Top 0.8: 44.8,1.74 44.76,85.06
  Bottom 0.2: 44.22,2.33 44.77,1.79
  other vias: 44.82,1.7
N$X.137  (via drill 0.2)  (1 unrouted)
  Bottom 0.2: 40.6,83.38 41.15,82.84
  other vias: 41.2,82.74
N$X.138  (via drill 0.2)  (1 unrouted)
  Bottom 0.2: 42.42,83.31 42.97,82.77
  other vias: 43.02,82.67
N$X.139  (via drill 0.2)  (1 unrouted)
  Bottom 0.2: 44.22,83.34 44.77,82.79
  other vias: 44.82,82.7
N$X.140  (via drill 0.2)  (1 unrouted)
  Bottom 0.2: 44.22,80.73 44.77,80.18
  other vias: 44.82,80.09
N$X.141  (via drill 0.2)  (1 unrouted)
  Bottom 0.2: 42.4,80.73 42.95,80.18
  other vias: 43,80.09
N$X.142  (via drill 0.2)  (1 unrouted)
  Bottom 0.2: 40.6,80.73 41.15,80.18
  other vias: 41.2,80.09
N$X.143  (via drill 0.2)  (1 unrouted)
  Bottom 0.2: 40.63,78.17 41.17,77.62
  other vias: 41.23,77.53
N$X.144  (via drill 0.2)  (1 unrouted)
  Bottom 0.2: 42.36,78.17 42.9,77.62
  other vias: 42.96,77.53
N$X.145  (via drill 0.2)  (1 unrouted)
  Bottom 0.2: 44.2,78.12 44.75,77.58
  other vias: 44.8,77.48
N$X.146  (via drill 0.2)  (1 unrouted)
  Bottom 0.2: 45.95,83.32 46.5,82.78
  other vias: 46.55,82.68
N$X.147  (via drill 0.2)  (1 unrouted)
  Bottom 0.2: 47.77,83.31 48.32,82.77
  other vias: 48.37,82.67
N$X.148  (via drill 0.2)  (1 unrouted)
  Bottom 0.2: 49.57,83.31 50.12,82.77
  other vias: 50.17,82.67
N$X.149  (via drill 0.2)  (1 unrouted)
  Bottom 0.2: 51.39,83.31 51.94,82.77
  other vias: 51.99,82.67
N$X.150  (via drill 0.2)  (1 unrouted)
  Bottom 0.2: 53.17,83.31 53.71,82.77
  other vias: 53.77,82.67
N$X.151  (via drill 0.2)  (1 unrouted)
  Bottom 0.2: 55.01,83.36 55.56,82.81
  other vias: 55.61,82.72
N$X.152  (via drill 0.2)  (1 unrouted)
  Bottom 0.2: 56.79,83.34 57.33,82.79
  other vias: 57.39,82.7
N$X.153  (via drill 0.2)  (1 unrouted)
  Bottom 0.2: 58.61,83.31 59.15,82.77
  other vias: 59.21,82.67
N$X.154  (via drill 0.2)  (1 unrouted)
  Bottom 0.2: 60.38,83.36 60.93,82.81
  other vias: 60.98,82.72
N$X.155  (via drill 0.2)  (1 unrouted)
  Bottom 0.2: 62.2,83.29 62.75,82.75
  other vias: 62.8,82.65
N$X.156  (via drill 0.2)  (1 unrouted)
  Bottom 0.2: 64.03,83.31 64.57,82.77
  other vias: 64.62,82.67
N$X.157  (via drill 0.2)  (1 unrouted)
  Bottom 0.2: 46,80.73 46.54,80.18
  other vias: 46.6,80.09
N$X.158  (via drill 0.2)  (5 unrouted)
  Top 0.8: 46.62,77.59 46.62,85.03 | 46.62,1.68 46.62,77.56
  Bottom 0.2: 46.02,78.17 46.57,77.62 | 45.98,2.38 46.52,1.83
  other vias: 46.62,77.53 46.57,1.74
N$X.159  (via drill 0.2)  (1 unrouted)
  Bottom 0.2: 46,75.58 46.54,75.04
  other vias: 46.6,74.94
N$X.160  (via drill 0.2)  (1 unrouted)
  Bottom 0.2: 110.22,38.38 109.45,39.14 109.12,39.14
  other vias: 110.2,38.42
N$X.161  (via drill 0.2)
  Bottom 0.2: v110.24,41.04 109.64,41.64 109.47,41.78
N$X.162  (via drill 0.2)  (1 unrouted)
  Bottom 0.2: 110.27,43.83 110.27,43.88 109.72,44.43
  other vias: 110.24,43.69
N$X.163  (via drill 0.2)
  Bottom 0.2: v110.22,46.23 110.17,46.33 109.57,46.93
N$X.164  (via drill 0.2)  (1 unrouted)
  Bottom 0.2: 45.84,73.02 46.39,72.47
  other vias: 46.44,72.38
N$X.165  (via drill 0.2)  (1 unrouted)
  Bottom 0.2: 47.8,73.02 48.34,72.47
  other vias: 48.39,72.38
N$X.166  (via drill 0.2)  (1 unrouted)
  Bottom 0.2: 101.69,59.4 101.14,59.94 100.79,59.94
  other vias: 101.64,59.38
N$X.167  (via drill 0.2)  (1 unrouted)
  Bottom 0.2: 47.77,75.58 48.32,75.04
  other vias: 48.37,74.94
N$X.168  (via drill 0.2)  (1 unrouted)
  Bottom 0.2: 47.77,78.14 48.32,77.6
  other vias: 48.37,77.5
N$X.169  (via drill 0.2)  (1 unrouted)
  Bottom 0.2: 47.8,80.73 48.34,80.18
  other vias: 48.39,80.09
N$X.170  (via drill 0.2)  (4 unrouted)
  Top 0.8: 50.21,1.65 50.13,85
  Bottom 0.2: 49.57,80.73 50.12,80.18 | 49.57,2.38 50.12,1.83
  other vias: 50.17,80.09 50.17,1.74
N$X.171  (via drill 0.2)  (1 unrouted)
  Bottom 0.2: 49.59,78.14 50.14,77.6
  other vias: 50.19,77.5
N$X.172  (via drill 0.2)  (1 unrouted)
  Bottom 0.2: 49.59,75.58 50.14,75.04
  other vias: 50.19,74.94
N$X.173  (via drill 0.2)  (1 unrouted)
  Bottom 0.2: 49.62,73.06 50.16,72.52
  other vias: 50.22,72.43
N$X.174  (via drill 0.2)  (1 unrouted)
  Bottom 0.2: 51.46,73.06 52.01,72.52
  other vias: 52.06,72.43
N$X.175  (via drill 0.2)  (1 unrouted)
  Bottom 0.2: 51.44,75.6 51.98,75.06
  other vias: 52.04,74.97
N$X.176  (via drill 0.2)  (1 unrouted)
  Bottom 0.2: 51.42,78.17 51.96,77.62
  other vias: 52.01,77.53
N$X.177  (via drill 0.2)  (1 unrouted)
  Bottom 0.2: 51.42,80.77 51.96,80.23
  other vias: 52.01,80.14
N$X.178  (via drill 0.2)  (4 unrouted)
  Top 0.8: 53.78,84.93 53.79,84.21 53.79,1.68
  Bottom 0.2: 53.19,80.75 53.74,80.2 | 53.19,2.33 53.74,1.79
  other vias: 53.79,80.11 53.79,1.7
N$X.179  (via drill 0.2)  (1 unrouted)
  Bottom 0.2: 53.21,78.17 53.76,77.62
  other vias: 53.81,77.53
N$X.180  (via drill 0.2)  (1 unrouted)
  Bottom 0.2: 53.26,75.6 53.8,75.06
  other vias: 53.86,74.97
N$X.181  (via drill 0.2)  (1 unrouted)
  Bottom 0.2: 53.21,73.04 53.76,72.5
  other vias: 53.81,72.4
N$X.182  (via drill 0.2)  (1 unrouted)
  Bottom 0.2: 55.01,73.04 55.56,72.5
  other vias: 55.61,72.4
N$X.183  (via drill 0.2)  (1 unrouted)
  Bottom 0.2: 55.01,75.63 55.56,75.08
  other vias: 55.61,74.99
N$X.184  (via drill 0.2)  (1 unrouted)
  Bottom 0.2: 55.03,78.19 55.58,77.64
  other vias: 55.63,77.55
N$X.185  (via drill 0.2)  (1 unrouted)
  Bottom 0.2: 55.01,80.73 55.56,80.18
  other vias: 55.61,80.09
N$X.186  (via drill 0.2)  (4 unrouted)
  Top 0.5: 57.41,84.53 57.41,85 | 57.41,1.74 57.38,1.74
  Top 0.8: 57.41,1.74 57.41,84.53
  Bottom 0.2: 56.79,80.73 57.33,80.18 | 56.77,2.36 57.31,1.81
  other vias: 57.39,80.09 57.36,1.72
N$X.187  (via drill 0.2)  (1 unrouted)
  Bottom 0.2: 56.79,78.17 57.33,77.62
  other vias: 57.39,77.53
N$X.188  (via drill 0.2)  (1 unrouted)
  Bottom 0.2: 56.88,75.58 57.42,75.04
  other vias: 57.48,74.94
N$X.189  (via drill 0.2)  (1 unrouted)
  Bottom 0.2: 56.83,73.06 57.38,72.52
  other vias: 57.43,72.43
N$X.190  (via drill 0.2)  (1 unrouted)
  Bottom 0.2: 58.61,73.02 59.15,72.47
  other vias: 59.21,72.38
N$X.191  (via drill 0.2)  (1 unrouted)
  Bottom 0.2: 108.5,38.45 107.67,39.28 107.41,39.28
  other vias: 108.52,38.42
N$X.192  (via drill 0.2)
  Bottom 0.2: v108.47,41.05 108.57,41.08 107.97,41.68
N$X.193  (via drill 0.2)  (1 unrouted)
  Bottom 0.2: 108.52,43.73 108.52,43.78 107.97,44.33
  other vias: 108.53,43.68
N$X.194  (via drill 0.2)
  Bottom 0.2: v108.47,46.23 108.31,46.23 107.82,46.83
N$X.195  (via drill 0.2)  (1 unrouted)
  Bottom 0.2: 58.59,75.6 59.13,75.06
  other vias: 59.18,74.97
N$X.196  (via drill 0.2)  (1 unrouted)
  Bottom 0.2: 58.59,78.17 59.13,77.62
  other vias: 59.18,77.53
N$X.197  (via drill 0.2)  (1 unrouted)
  Bottom 0.2: 58.59,80.73 59.13,80.18
  other vias: 59.18,80.09
N$X.198  (via drill 0.2)  (1 unrouted)
  Bottom 0.2: 60.38,80.73 60.93,80.18
  other vias: 60.98,80.09
N$X.199  (via drill 0.2)  (1 unrouted)
  Bottom 0.2: 60.38,78.17 60.93,77.62
  other vias: 60.98,77.53
N$X.200  (via drill 0.2)  (1 unrouted)
  Bottom 0.2: 60.38,75.6 60.93,75.06
  other vias: 60.98,74.97
N$X.201  (via drill 0.2)  (1 unrouted)
  Bottom 0.2: 60.38,73.04 60.93,72.5
  other vias: 60.98,72.4
N$X.202  (via drill 0.2)  (1 unrouted)
  Bottom 0.2: 62.23,80.7 62.77,80.16
  other vias: 62.83,80.07
N$X.203  (via drill 0.2)  (1 unrouted)
  Bottom 0.2: 64.07,80.7 64.62,80.16
  other vias: 64.67,80.07
N$X.204  (via drill 0.2)  (1 unrouted)
  Bottom 0.2: 62.18,78.19 62.73,77.64
  other vias: 62.78,77.55
N$X.205  (via drill 0.2)  (1 unrouted)
  Bottom 0.2: 63.96,78.17 64.5,77.62
  other vias: 64.56,77.53
N$X.206  (via drill 0.2)  (1 unrouted)
  Bottom 0.2: 62.2,75.54 62.75,74.99
  other vias: 62.8,74.9
N$X.207  (via drill 0.2)  (1 unrouted)
  Bottom 0.2: 64.07,75.56 64.62,75.01
  other vias: 64.67,74.92
N$X.208  (via drill 0.2)  (1 unrouted)
  Bottom 0.2: 62.2,73.06 62.75,72.52
  other vias: 62.8,72.43
N$X.209  (via drill 0.2)  (1 unrouted)
  Bottom 0.2: 64.05,73.06 64.59,72.52
  other vias: 64.65,72.43
N$X.210  (via drill 0.2)  (1 unrouted)
  Bottom 0.2: 40.6,62.57 41.15,62.02
  other vias: 41.2,61.93
N$X.211  (via drill 0.2)  (1 unrouted)
  Bottom 0.2: 42.92,61.95 42.38,62.5
  other vias: 42.98,61.86
N$X.212  (via drill 0.2)  (1 unrouted)
  Bottom 0.2: 44.77,62.02 44.22,62.57
  other vias: 44.82,61.93
N$X.213  (via drill 0.2)  (1 unrouted)
  Bottom 0.2: 46.57,62 46.02,62.55
  other vias: 46.62,61.91
N$X.214  (via drill 0.2)  (1 unrouted)
  Bottom 0.2: 48.27,62.02 47.73,62.57
  other vias: 48.33,61.93
N$X.215  (via drill 0.2)  (1 unrouted)
  Bottom 0.2: 50.19,62.02 49.64,62.57
  other vias: 50.24,61.93
N$X.216  (via drill 0.2)  (1 unrouted)
  Bottom 0.2: 51.98,62.02 51.44,62.57
  other vias: 52.04,61.93
N$X.217  (via drill 0.2)  (1 unrouted)
  Bottom 0.2: 53.19,62.55 53.74,62
  other vias: 53.79,61.91
N$X.218  (via drill 0.2)  (1 unrouted)
  Bottom 0.2: 55.56,62.05 55.01,62.59
  other vias: 55.61,61.95
N$X.219  (via drill 0.2)  (1 unrouted)
  Bottom 0.2: 57.4,62 56.86,62.55
  other vias: 57.45,61.91
N$X.220  (via drill 0.2)  (1 unrouted)
  Bottom 0.2: 106.78,33.17 106.19,33.77 105.85,33.77
  other vias: 106.75,33.19
N$X.221  (via drill 0.2)  (1 unrouted)
  Bottom 0.2: v106.77,35.8 105.86,36.71 105.75,36.71
N$X.222  (via drill 0.2)  (1 unrouted)
  Bottom 0.2: 106.78,38.47 106,39.24 105.68,39.24
  other vias: 106.73,38.42
N$X.223  (via drill 0.2)
  Bottom 0.2: v106.69,41.08 106.07,41.62 106.16,41.47
N$X.224  (via drill 0.2)  (1 unrouted)
  Bottom 0.2: 106.77,43.83 106.77,43.88 106.22,44.43
  other vias: 106.74,43.7
N$X.225  (via drill 0.2)
  Bottom 0.2: v106.75,46.27 106.67,46.33 106.07,46.93
N$X.226  (via drill 0.2)  (1 unrouted)
  Bottom 0.2: 40.6,59.96 41.15,59.42
  other vias: 41.2,59.32
N$X.227  (via drill 0.2)  (1 unrouted)
  Bottom 0.2: 42.9,59.46 42.36,60.01
  other vias: 42.96,59.37
N$X.228  (via drill 0.2)  (1 unrouted)
  Bottom 0.2: 44.75,59.46 44.2,60.01
  other vias: 44.8,59.37
N$X.229  (via drill 0.2)  (1 unrouted)
  Bottom 0.2: 46.54,59.46 46,60.01
  other vias: 46.6,59.37
N$X.230  (via drill 0.2)  (1 unrouted)
  Bottom 0.2: 48.34,59.46 47.8,60.01
  other vias: 48.39,59.37
N$X.231  (via drill 0.2)  (1 unrouted)
  Bottom 0.2: 50.16,59.46 49.62,60.01
  other vias: 50.22,59.37
N$X.232  (via drill 0.2)  (1 unrouted)
  Bottom 0.2: 51.98,59.51 51.44,60.05
  other vias: 52.04,59.41
N$X.233  (via drill 0.2)  (1 unrouted)
  Bottom 0.2: 53.21,59.98 53.76,59.44
  other vias: 53.81,59.34
N$X.234  (via drill 0.2)  (1 unrouted)
  Bottom 0.2: 55.53,59.48 54.99,60.03
  other vias: 55.59,59.39
N$X.235  (via drill 0.2)  (1 unrouted)
  Bottom 0.2: 57.31,59.51 56.77,60.05
  other vias: 57.36,59.41
N$X.236  (via drill 0.2)  (1 unrouted)
  Bottom 0.2: 57.36,56.79 56.81,57.33
  other vias: 57.41,56.69
N$X.237  (via drill 0.2)  (1 unrouted)
  Bottom 0.2: 55.53,56.72 54.99,57.26
  other vias: 55.59,56.63
N$X.238  (via drill 0.2)  (1 unrouted)
  Bottom 0.2: 53.17,57.31 53.71,56.76
  other vias: 53.77,56.67
N$X.239  (via drill 0.2)  (1 unrouted)
  Bottom 0.2: 51.98,56.74 51.44,57.29
  other vias: 52.04,56.65
N$X.240  (via drill 0.2)  (1 unrouted)
  Bottom 0.2: 50.09,56.79 49.55,57.33
  other vias: 50.15,56.69
N$X.241  (via drill 0.2)  (1 unrouted)
  Bottom 0.2: 48.39,56.74 47.84,57.29
  other vias: 48.44,56.65
N$X.242  (via drill 0.2)  (1 unrouted)
  Bottom 0.2: 46.59,56.74 46.04,57.29
  other vias: 46.64,56.65
N$X.243  (via drill 0.2)  (1 unrouted)
  Bottom 0.2: 44.7,56.72 44.16,57.26
  other vias: 44.75,56.63
N$X.244  (via drill 0.2)  (1 unrouted)
  Bottom 0.2: 42.95,56.7 42.4,57.24
  other vias: 43,56.6
N$X.245  (via drill 0.2)  (1 unrouted)
  Bottom 0.2: 40.65,57.26 41.19,56.72
  other vias: 41.25,56.63
N$X.246  (via drill 0.2)  (1 unrouted)
  Bottom 0.2: 40.65,54.57 41.19,54.02
  other vias: 41.25,53.93
N$X.247  (via drill 0.2)  (1 unrouted)
  Bottom 0.2: 42.92,54.02 42.38,54.57
  other vias: 42.98,53.93
N$X.248  (via drill 0.2)  (1 unrouted)
  Bottom 0.2: 44.7,54.02 44.16,54.57
  other vias: 44.75,53.93
N$X.249  (via drill 0.2)  (1 unrouted)
  Bottom 0.2: 45.98,54.54 46.52,54
  other vias: 46.57,53.91
N$X.250  (via drill 0.2)  (1 unrouted)
  Bottom 0.2: 47.82,54.52 48.37,53.98
  other vias: 48.42,53.88
N$X.251  (via drill 0.2)  (1 unrouted)
  Bottom 0.2: v105,33.17 104.38,33.79 104.35,33.79
N$X.252  (via drill 0.2)  (1 unrouted)
  Bottom 0.2: 105,35.83 104.33,36.5 104.25,36.5
  other vias: 105.03,35.84
N$X.253  (via drill 0.2)  (1 unrouted)
  Bottom 0.2: 105.02,38.42 104.39,39.05 104.22,39.05
  other vias: 105,38.46
N$X.254  (via drill 0.2)
  Bottom 0.2: v105,41.1 104.52,41.78
N$X.255  (via drill 0.2)  (1 unrouted)
  Bottom 0.2: 105.02,43.73 104.97,43.58 104.47,44.23
  other vias: 104.97,43.68
N$X.256  (via drill 0.2)
  Bottom 0.2: 105.02,46.28 104.42,46.88
  Bottom 0.5: v105.02,46.26 105.02,46.28
N$X.257  (via drill 0.2)  (1 unrouted)
  Bottom 0.2: 50.16,54.02 49.62,54.57
  other vias: 50.22,53.93
N$X.258  (via drill 0.2)  (1 unrouted)
  Bottom 0.2: 51.98,54.02 51.44,54.57
  other vias: 52.04,53.93
N$X.259  (via drill 0.2)  (1 unrouted)
  Bottom 0.2: 53.17,54.57 53.71,54.02
  other vias: 53.77,53.93
N$X.260  (via drill 0.2)  (1 unrouted)
  Bottom 0.2: 55.51,54.04 54.97,54.59
  other vias: 55.56,53.95
N$X.261  (via drill 0.2)  (1 unrouted)
  Bottom 0.2: 57.33,54.04 56.79,54.59
  other vias: 57.39,53.95
N$X.262  (via drill 0.2)  (1 unrouted)
  Bottom 0.2: 56.77,51.98 57.31,51.44
  other vias: 57.36,51.34
N$X.263  (via drill 0.2)  (1 unrouted)
  Bottom 0.2: 54.95,51.96 55.49,51.42
  other vias: 55.54,51.32
N$X.264  (via drill 0.2)  (1 unrouted)
  Bottom 0.2: 53.19,51.96 53.74,51.42
  other vias: 53.79,51.32
N$X.265  (via drill 0.2)  (1 unrouted)
  Bottom 0.2: 51.33,51.98 51.87,51.44
  other vias: 51.92,51.34
N$X.266  (via drill 0.2)  (1 unrouted)
  Bottom 0.2: 49.62,51.98 50.16,51.44
  other vias: 50.22,51.34
N$X.267  (via drill 0.2)  (1 unrouted)
  Bottom 0.2: 47.8,51.94 48.34,51.39
  other vias: 48.39,51.3
N$X.268  (via drill 0.2)  (1 unrouted)
  Bottom 0.2: 45.98,51.92 46.52,51.37
  other vias: 46.57,51.28
N$X.269  (via drill 0.2)  (1 unrouted)
  Bottom 0.2: 44.2,51.98 44.75,51.44
  other vias: 44.8,51.34
N$X.270  (via drill 0.2)  (1 unrouted)
  Bottom 0.2: 42.42,51.94 42.97,51.39
  other vias: 43.02,51.3
N$X.271  (via drill 0.2)  (1 unrouted)
  Bottom 0.2: 40.6,51.94 41.15,51.39
  other vias: 41.2,51.3
N$X.272  (via drill 0.2)  (1 unrouted)
  Bottom 0.2: 31.61,46.79 32.16,46.25
  other vias: 32.21,46.15
N$X.273  (via drill 0.2)  (1 unrouted)
  Bottom 0.2: 33.39,46.77 33.93,46.22
  other vias: 33.99,46.13
N$X.274  (via drill 0.2)  (1 unrouted)
  Bottom 0.2: 35.23,46.81 35.78,46.27
  other vias: 35.83,46.17
N$X.275  (via drill 0.2)  (1 unrouted)
  Bottom 0.2: 37.01,46.79 37.55,46.25
  other vias: 37.61,46.15
N$X.276  (via drill 0.2)  (1 unrouted)
  Bottom 0.2: 38.83,46.81 39.37,46.27
  other vias: 39.43,46.17
N$X.277  (via drill 0.2)  (1 unrouted)
  Bottom 0.2: 38.81,44.3 39.35,43.75
  other vias: 39.4,43.66
N$X.278  (via drill 0.2)  (1 unrouted)
  Bottom 0.2: 37.03,44.27 37.57,43.73
  other vias: 37.63,43.64
N$X.279  (via drill 0.2)  (1 unrouted)
  Bottom 0.2: 35.19,44.25 35.73,43.7
  other vias: 35.78,43.61
N$X.280  (via drill 0.2)  (1 unrouted)
  Bottom 0.2: 33.46,44.27 34,43.73
  other vias: 34.05,43.64
N$X.281  (via drill 0.2)  (1 unrouted)
  Bottom 0.2: 31.66,44.3 32.2,43.75
  other vias: 32.26,43.66
N$X.282
  Bottom 0.2: 103.36,33.13 102.59,33.91 102.22,33.91
N$X.283
  Bottom 0.2: 103.39,35.81 102.6,36.6 102.22,36.6
N$X.284
  Bottom 0.2: 103.31,38.48 102.61,39.18 102.22,39.18
N$X.285  (via drill 0.2)
  Bottom 0.2: 103.32,41.03 102.72,41.63
  Bottom 0.5: v103.27,41.03 103.32,41.03
N$X.286  (via drill 0.2)
  Bottom 0.2: 103.22,43.68 102.67,44.23
  Bottom 0.5: v103.27,43.68 103.22,43.68
N$X.287  (via drill 0.2)  (1 unrouted)
  Bottom 0.2: 103.21,46.2 102.39,47.01 102.2,47.01
  other vias: 103.22,46.22
N$X.288  (via drill 0.2)  (1 unrouted)
  Bottom 0.2: 29.84,41.69 30.38,41.14
  other vias: 30.44,41.05
N$X.289  (via drill 0.2)  (1 unrouted)
  Bottom 0.2: 31.64,41.71 32.18,41.17
  other vias: 32.23,41.07
N$X.290  (via drill 0.2)  (1 unrouted)
  Bottom 0.2: 33.46,41.67 34,41.12
  other vias: 34.05,41.03
N$X.291  (via drill 0.2)  (1 unrouted)
  Bottom 0.2: 35.25,41.64 35.8,41.1
  other vias: 35.85,41
N$X.292  (via drill 0.2)  (1 unrouted)
  Bottom 0.2: 36.99,41.69 37.53,41.14
  other vias: 37.58,41.05
N$X.293  (via drill 0.2)  (1 unrouted)
  Bottom 0.2: 37.01,39.1 37.55,38.56
  other vias: 37.61,38.47
N$X.294  (via drill 0.2)  (1 unrouted)
  Bottom 0.2: 35.25,39.08 35.8,38.54
  other vias: 35.85,38.44
N$X.295  (via drill 0.2)  (1 unrouted)
  Bottom 0.2: 33.48,39.1 34.02,38.56
  other vias: 34.08,38.47
N$X.296  (via drill 0.2)  (1 unrouted)
  Bottom 0.2: 31.64,39.08 32.18,38.54
  other vias: 32.23,38.44
N$X.297  (via drill 0.2)  (1 unrouted)
  Bottom 0.2: 29.81,39.04 30.36,38.49
  other vias: 30.41,38.4
N$X.298  (via drill 0.2)  (1 unrouted)
  Bottom 0.2: 38.78,41.69 39.33,41.14
  other vias: 39.38,41.05
N$X.299  (via drill 0.2)  (1 unrouted)
  Bottom 0.2: 38.85,39.13 39.4,38.58
  other vias: 39.45,38.49
N$X.300  (via drill 0.2)  (1 unrouted)
  Bottom 0.2: 58.56,49.38 59.11,48.83
  other vias: 59.16,48.74
N$X.301  (via drill 0.2)  (1 unrouted)
  Bottom 0.2: 56.77,49.38 57.31,48.83
  other vias: 57.36,48.74
N$X.302  (via drill 0.2)  (1 unrouted)
  Bottom 0.2: 54.97,49.38 55.51,48.83
  other vias: 55.56,48.74
N$X.303  (via drill 0.2)  (1 unrouted)
  Bottom 0.2: 53.24,49.33 53.78,48.78
  other vias: 53.84,48.69
N$X.304  (via drill 0.2)  (1 unrouted)
  Bottom 0.2: 51.37,49.38 51.92,48.83
  other vias: 51.97,48.74
N$X.305  (via drill 0.2)  (1 unrouted)
  Bottom 0.2: 49.59,49.38 50.14,48.83
  other vias: 50.19,48.74
N$X.306  (via drill 0.2)  (1 unrouted)
  Bottom 0.2: 47.82,49.42 48.37,48.88
  other vias: 48.42,48.78
N$X.307  (via drill 0.2)  (1 unrouted)
  Bottom 0.2: 46,49.38 46.54,48.83
  other vias: 46.6,48.74
N$X.308  (via drill 0.2)  (1 unrouted)
  Bottom 0.2: 44.22,49.38 44.77,48.83
  other vias: 44.82,48.74
N$X.309  (via drill 0.2)  (1 unrouted)
  Bottom 0.2: 42.36,49.4 42.9,48.85
  other vias: 42.96,48.76
N$X.310  (via drill 0.2)  (1 unrouted)
  Bottom 0.2: 40.6,49.4 41.15,48.85
  other vias: 41.2,48.76
N$X.311  (via drill 0.2)  (1 unrouted)
  Bottom 0.2: 58.56,46.88 59.11,46.33
  other vias: 59.16,46.24
N$X.312  (via drill 0.2)  (1 unrouted)
  Bottom 0.2: 56.79,46.83 57.33,46.29
  other vias: 57.39,46.2
N$X.313  (via drill 0.2)  (1 unrouted)
  Bottom 0.2: 101.55,33.17 100.94,33.78 100.93,33.78
  other vias: 101.53,33.19
N$X.314  (via drill 0.2)  (1 unrouted)
  Bottom 0.2: 101.47,35.79 100.83,36.43 100.36,36.43
  other vias: 101.54,35.82
N$X.315  (via drill 0.2)  (1 unrouted)
  Bottom 0.2: 101.56,38.44 100.8,39.21 100.61,39.21
  other vias: 101.55,38.44
N$X.316  (1 unrouted)
  Bottom 0.2: 101.58,41.06 100.83,41.81 100.56,41.81 | 100.82,41.59 100.92,41.73
N$X.317  (via drill 0.2)
  Bottom 0.2: 101.57,43.73 v101.52,43.68 100.97,44.23
N$X.318  (via drill 0.2)  (1 unrouted)
  Bottom 0.2: v101.54,46.21 100.87,46.88 100.52,46.88
N$X.319  (via drill 0.2)  (1 unrouted)
  Bottom 0.2: 54.99,46.83 55.53,46.29
  other vias: 55.59,46.2
N$X.320  (via drill 0.2)  (1 unrouted)
  Bottom 0.2: 53.19,46.79 53.74,46.25
  other vias: 53.79,46.15
N$X.321  (via drill 0.2)  (1 unrouted)
  Bottom 0.2: 51.42,46.83 51.96,46.29
  other vias: 52.01,46.2
N$X.322  (via drill 0.2)  (1 unrouted)
  Bottom 0.2: 49.64,46.81 50.19,46.27
  other vias: 50.24,46.17
N$X.323  (via drill 0.2)  (1 unrouted)
  Bottom 0.2: 47.77,46.79 48.32,46.25
  other vias: 48.37,46.15
N$X.324  (via drill 0.2)  (1 unrouted)
  Bottom 0.2: 46,46.81 46.54,46.27
  other vias: 46.6,46.17
N$X.325  (via drill 0.2)  (1 unrouted)
  Bottom 0.2: 44.22,46.79 44.77,46.25
  other vias: 44.82,46.15
N$X.326  (via drill 0.2)  (1 unrouted)
  Bottom 0.2: 42.45,46.81 42.99,46.27
  other vias: 43.05,46.17
N$X.327  (via drill 0.2)  (1 unrouted)
  Bottom 0.2: 40.6,46.86 41.15,46.31
  other vias: 41.2,46.22
N$X.328  (via drill 0.2)  (1 unrouted)
  Bottom 0.2: 58.56,44.3 59.11,43.75
  other vias: 59.16,43.66
N$X.329  (via drill 0.2)  (1 unrouted)
  Bottom 0.2: 56.79,44.25 57.33,43.7
  other vias: 57.39,43.61
N$X.330  (via drill 0.2)  (1 unrouted)
  Bottom 0.2: 55.01,44.27 55.56,43.73
  other vias: 55.61,43.64
N$X.331  (via drill 0.2)  (1 unrouted)
  Bottom 0.2: 53.19,44.25 53.74,43.7
  other vias: 53.79,43.61
N$X.332  (via drill 0.2)  (1 unrouted)
  Bottom 0.2: 51.42,44.27 51.96,43.73
  other vias: 52.01,43.64
N$X.333  (via drill 0.2)  (1 unrouted)
  Bottom 0.2: 49.55,44.3 50.09,43.75
  other vias: 50.15,43.66
N$X.334  (via drill 0.2)  (1 unrouted)
  Bottom 0.2: 47.73,44.27 48.27,43.73
  other vias: 48.33,43.64
N$X.335  (via drill 0.2)  (1 unrouted)
  Bottom 0.2: 46,44.27 46.54,43.73
  other vias: 46.6,43.64
N$X.336  (via drill 0.2)  (1 unrouted)
  Bottom 0.2: 44.2,44.25 44.75,43.7
  other vias: 44.8,43.61
N$X.337  (via drill 0.2)  (1 unrouted)
  Bottom 0.2: 42.38,44.3 42.92,43.75
  other vias: 42.98,43.66
N$X.338  (via drill 0.2)  (1 unrouted)
  Bottom 0.2: 40.63,44.27 41.17,43.73
  other vias: 41.23,43.64
N$X.339  (via drill 0.2)  (1 unrouted)
  Bottom 0.2: 58.54,41.64 59.09,41.1
  other vias: 59.14,41
N$X.340  (via drill 0.2)  (1 unrouted)
  Bottom 0.2: 56.77,41.64 57.31,41.1
  other vias: 57.36,41
N$X.341  (via drill 0.2)  (1 unrouted)
  Bottom 0.2: 54.99,41.67 55.53,41.12
  other vias: 55.59,41.03
N$X.342  (via drill 0.2)  (1 unrouted)
  Bottom 0.2: 53.15,41.67 53.69,41.12
  other vias: 53.74,41.03
N$X.343  (via drill 0.2)  (1 unrouted)
  Bottom 0.2: 51.42,41.64 51.96,41.1
  other vias: 52.01,41
N$X.344  (via drill 0.2)  (1 unrouted)
  Bottom 0.2: 99.8,33.15 99.03,33.92 98.89,33.92
  other vias: 99.78,33.19
N$X.345  (via drill 0.2)  (1 unrouted)
  Bottom 0.2: 99.71,35.79 98.98,36.51 98.6,36.51
  other vias: 99.75,35.8
N$X.346  (via drill 0.2)  (1 unrouted)
  Bottom 0.2: 99.83,38.47 99.19,39.1 98.98,39.1
  other vias: 99.8,38.44
N$X.347  (via drill 0.2)  (2 unrouted)
  Bottom 0.2: 99.27,41.78 99.17,41.68 | 99.75,41.07 99.06,41.76 98.89,41.76
  other vias: 99.82,41.09
N$X.348  (via drill 0.2)
  Bottom 0.2: 99.02,44.28 v99.72,43.66
N$X.349  (via drill 0.2)  (1 unrouted)
  Bottom 0.2: 99.74,46.21 99.08,46.87 98.69,46.87
  other vias: 99.75,46.23
N$X.350  (via drill 0.2)  (1 unrouted)
  Bottom 0.2: 49.62,41.62 50.16,41.08
  other vias: 50.22,40.98
N$X.351  (via drill 0.2)  (1 unrouted)
  Bottom 0.2: 47.8,41.6 48.34,41.05
  other vias: 48.39,40.96
N$X.352  (via drill 0.2)  (1 unrouted)
  Bottom 0.2: 46.04,41.6 46.59,41.05
  other vias: 46.64,40.96
N$X.353  (via drill 0.2)  (1 unrouted)
  Bottom 0.2: 44.25,41.62 44.79,41.08
  other vias: 44.84,40.98
N$X.354  (via drill 0.2)  (1 unrouted)
  Bottom 0.2: 42.4,41.6 42.95,41.05
  other vias: 43,40.96
N$X.355  (via drill 0.2)  (1 unrouted)
  Bottom 0.2: 40.6,41.67 41.15,41.12
  other vias: 41.2,41.03
N$X.356  (via drill 0.2)  (1 unrouted)
  Bottom 0.2: 40.63,39.06 41.17,38.51
  other vias: 41.23,38.42
N$X.357  (via drill 0.2)  (1 unrouted)
  Bottom 0.2: 42.38,39.08 42.92,38.54
  other vias: 42.98,38.44
N$X.358  (via drill 0.2)  (1 unrouted)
